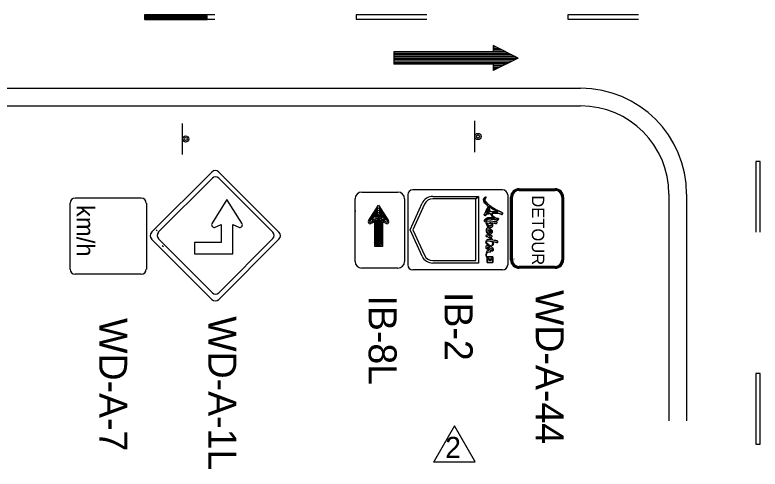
# Model space of a CAD drawing. Extents: x 1806 to 2022, y 110 to 389.
# Drawn here: x 1918.6 to 1969.6, y 190.1 to 221.2 of the extents above; entities that cross this region are included whole.
import ezdxf

# ---------------------------------------------------------------- set-up
doc = ezdxf.new("R2010")
doc.units = 0
for name, color, linetype in [('Level 10', 7, 'Continuous'), ('Level 2', 7, 'Continuous'), ('Level 44', 7, 'Continuous'), ('Level 50', 7, 'Continuous'), ('Level 53', 7, 'Continuous'), ('Level 60', 7, 'Continuous')]:
    doc.layers.add(name, color=color, linetype=linetype)

msp = doc.modelspace()

# ---------------------------------------------------------------- linework, layer by layer
at = {"layer": 'Level 10'}
for p, q in [((1927.465, 221.11), (1931.732, 221.11)), ((1927.465, 220.854), (1927.465, 221.11)), ((1927.465, 221.046), (1931.732, 221.046)), ((1927.465, 220.982), (1931.732, 220.982)), ((1927.465, 220.918), (1931.732, 220.918)), ((1927.465, 220.854), (1931.732, 220.854)), ((1931.732, 220.854), (1931.732, 221.11)), ((1895.86, 216.139), (1957.331, 216.139)), ((1895.86, 214.93), (1957.331, 214.93)), ((1963.38, 208.881), (1963.38, 193.374)), ((1964.59, 208.881), (1964.59, 193.374))]:
    msp.add_line(p, q, dxfattribs=at)
for radius in [7.258, 6.048]:
    msp.add_arc((1957.332, 208.881), radius, 0, 90, dxfattribs=at)
at = {"layer": 'Level 2'}
for p, q in [((1932.271, 221.163), (1927.433, 221.163)), ((1927.433, 221.163), (1927.433, 220.873)), ((1946.785, 221.163), (1941.947, 221.163)), ((1941.947, 221.163), (1941.947, 220.873)), ((1961.299, 221.163), (1956.461, 221.163)), ((1956.461, 221.163), (1956.461, 220.873)), ((1927.433, 220.873), (1932.271, 220.873)), ((1941.947, 220.873), (1946.785, 220.873)), ((1956.461, 220.873), (1961.299, 220.873)), ((1969.337, 211.124), (1969.337, 206.286)), ((1969.627, 211.124), (1969.337, 211.124)), ((1969.627, 206.286), (1969.627, 211.124)), ((1951.985, 209.179), (1945.831, 209.179)), ((1945.484, 208.832), (1945.484, 204.048)), ((1947.192, 208.737), (1950.32, 208.737)), ((1950.148, 208.566), (1947.192, 208.566)), ((1950.32, 208.737), (1950.148, 208.566)), ((1950.148, 208.566), (1950.32, 208.737)), ((1950.148, 204.343), (1950.148, 208.566)), ((1950.32, 208.737), (1950.32, 204.171)), ((1952.332, 208.832), (1952.332, 204.048)), ((1952.332, 208.832), (1952.332, 204.048)), ((1945.64, 206.454), (1946.465, 208.269)), ((1946.621, 208.198), (1945.828, 206.454)), ((1928.312, 206.367), (1928.234, 206.445)), ((1946.465, 204.64), (1945.64, 206.454)), ((1945.828, 206.454), (1946.621, 204.71)), ((1928.737, 205.274), (1928.659, 205.352)), ((1947.192, 204.343), (1950.148, 204.343)), ((1950.32, 204.171), (1947.192, 204.171)), ((1951.985, 203.701), (1945.831, 203.701)), ((1969.337, 196.61), (1969.337, 191.772)), ((1969.627, 196.61), (1969.337, 196.61)), ((1969.627, 191.772), (1969.627, 196.61)), ((1969.337, 191.772), (1969.627, 191.772))]:
    msp.add_line(p, q, dxfattribs=at)
for centre, radius, start, end in [((1945.831, 208.832), 0.347, 90, 180), ((1951.985, 208.832), 0.347, 360, 90), ((1947.192, 207.938), 0.799, 90, 155.5432), ((1947.192, 207.938), 0.628, 90, 155.5432), ((1947.192, 204.97), 0.799, 204.4568, 270), ((1947.192, 204.97), 0.628, 204.4568, 270), ((1945.831, 204.048), 0.347, 180, 270), ((1951.985, 204.048), 0.347, 270, 360)]:
    msp.add_arc(centre, radius, start, end, dxfattribs=at)
at = {"layer": 'Level 44'}
for p, q in [((1930.019, 213.734), (1930.019, 211.601)), ((1950.058, 213.907), (1950.058, 211.774)), ((1932.049, 210.401), (1927.931, 206.28)), ((1932.049, 210.397), (1932.049, 210.401)), ((1936.651, 206.28), (1932.537, 210.401)), ((1928.389, 206.28), (1932.094, 209.988)), ((1932.534, 209.988), (1936.237, 206.28)), ((1942.336, 209.022), (1944.801, 209.022)), ((1953.114, 209.142), (1955.579, 209.142)), ((1953.115, 209.256), (1955.58, 209.256)), ((1953.115, 209.191), (1955.58, 209.191)), ((1953.115, 209.137), (1955.58, 209.137)), ((1953.115, 209.137), (1955.58, 209.137)), ((1922.688, 208.625), (1922.689, 208.625)), ((1922.689, 208.625), (1927.219, 208.625)), ((1933.093, 208.511), (1932.071, 206.906)), ((1934.118, 206.903), (1933.093, 208.511)), ((1941.871, 204.275), (1941.871, 208.566)), ((1945.258, 208.566), (1945.258, 204.275)), ((1952.533, 204.39), (1952.533, 208.681)), ((1952.598, 204.39), (1952.598, 208.681)), ((1952.651, 204.395), (1952.651, 208.686)), ((1952.652, 204.39), (1952.652, 208.681)), ((1952.652, 204.39), (1952.652, 208.681)), ((1956.035, 208.686), (1956.035, 204.395)), ((1956.036, 208.681), (1956.036, 204.39)), ((1956.036, 208.681), (1956.036, 204.39)), ((1956.09, 208.681), (1956.09, 204.39)), ((1956.155, 208.681), (1956.155, 204.39)), ((1922.34, 203.747), (1922.34, 208.275)), ((1927.568, 208.275), (1927.568, 203.747)), ((1942.798, 207.055), (1943.481, 208.13)), ((1943.481, 208.13), (1944.168, 207.055)), ((1943.217, 206.982), (1942.909, 206.85)), ((1943.217, 205.305), (1943.217, 206.978)), ((1944.057, 206.854), (1943.75, 206.982)), ((1943.75, 206.982), (1943.75, 205.305)), ((1932.239, 206.604), (1932.702, 206.802)), ((1932.702, 206.802), (1932.702, 205.585)), ((1933.493, 204.794), (1933.493, 206.799)), ((1933.493, 206.799), (1933.951, 206.598)), ((1952.645, 206.32), (1952.645, 206.32)), ((1952.646, 206.315), (1952.646, 206.315)), ((1952.646, 206.315), (1952.646, 206.315)), ((1932.094, 202.139), (1928.389, 205.842)), ((1936.237, 205.842), (1932.534, 202.139)), ((1927.931, 205.794), (1932.049, 201.68)), ((1932.702, 205.585), (1930.858, 205.585)), ((1930.858, 205.585), (1930.858, 204.794)), ((1932.537, 201.68), (1936.651, 205.794)), ((1943.75, 205.305), (1943.217, 205.305)), ((1930.858, 204.794), (1933.493, 204.794)), ((1952.65, 204.394), (1952.652, 204.39)), ((1952.698, 204.418), (1952.7, 204.414)), ((1952.756, 204.447), (1952.758, 204.443)), ((1944.801, 203.823), (1942.336, 203.823)), ((1955.579, 203.943), (1953.114, 203.943)), ((1955.58, 203.938), (1953.115, 203.938)), ((1955.58, 203.938), (1953.115, 203.938)), ((1955.58, 203.884), (1953.115, 203.884)), ((1955.58, 203.819), (1953.115, 203.819)), ((1927.219, 203.397), (1922.689, 203.397))]:
    msp.add_line(p, q, dxfattribs=at)
for points in [[(1943.298, 205.395), (1943.298, 207.11), (1942.901, 206.94), (1942.858, 206.986), (1943.481, 207.972), (1944.113, 206.982), (1944.087, 206.935), (1943.665, 207.11), (1943.665, 205.391), (1943.298, 205.395), (1943.387, 205.476), (1943.387, 207.238), (1943.02, 207.089), (1943.481, 207.81), (1943.942, 207.089), (1943.575, 207.238), (1943.575, 205.476), (1943.387, 205.476), (1943.473, 205.566), (1943.473, 207.379), (1943.242, 207.281), (1943.481, 207.652), (1943.724, 207.272), (1943.588, 207.328), (1943.481, 207.498), (1943.374, 207.336), (1943.485, 207.37), (1943.588, 207.328), (1943.528, 207.242), (1943.485, 205.57), (1943.473, 205.566)], [(1941.867, 207.772), (1941.867, 207.7)], [(1943.298, 205.395), (1943.298, 207.11)]]:
    msp.add_lwpolyline(points, dxfattribs=at)
for centre, radius in [((1950.297, 212.836), 0.213), ((1930.258, 212.663), 0.213), ((1930.258, 212.663), 0.107), ((1950.297, 212.836), 0.107)]:
    msp.add_circle(centre, radius, dxfattribs=at)
for centre, radius, start, end in [((1932.293, 210.154), 0.345, 45, 135), ((1932.314, 209.767), 0.31, 45, 135), ((1942.333, 208.565), 0.462, 90, 180), ((1944.802, 208.565), 0.462, 0, 90), ((1953.111, 208.681), 0.581, 90, 180), ((1953.111, 208.681), 0.516, 90, 180), ((1953.11, 208.686), 0.462, 90, 180), ((1953.111, 208.681), 0.462, 90, 180), ((1953.111, 208.681), 0.462, 90, 180), ((1955.58, 208.686), 0.462, 0, 90), ((1955.581, 208.681), 0.581, 0, 90), ((1955.581, 208.681), 0.516, 0, 90), ((1955.581, 208.681), 0.462, 0, 90), ((1955.581, 208.681), 0.462, 0, 90), ((1922.688, 208.275), 0.349, 90, 180), ((1927.217, 208.275), 0.349, 360, 90), ((1932.238, 206.801), 0.198, 147.5014, 269.8949), ((1933.951, 206.797), 0.198, 269.8942, 32.4962), ((1942.908, 206.983), 0.132, 147.5038, 270.1058), ((1944.056, 206.986), 0.132, 270.1051, 32.4986), ((1928.177, 206.038), 0.345, 135, 225), ((1928.609, 206.062), 0.31, 135, 225), ((1936.018, 206.062), 0.31, 315, 45), ((1936.409, 206.038), 0.345, 315, 45), ((1942.333, 204.279), 0.462, 180, 270), ((1944.802, 204.279), 0.462, 270, 360), ((1953.111, 204.394), 0.581, 180, 270), ((1953.111, 204.394), 0.516, 180, 270), ((1953.11, 204.399), 0.462, 180, 270), ((1953.111, 204.394), 0.462, 180, 270), ((1953.111, 204.394), 0.462, 180, 270), ((1955.58, 204.399), 0.462, 270, 360), ((1955.581, 204.394), 0.462, 270, 360), ((1955.581, 204.394), 0.581, 270, 360), ((1955.581, 204.394), 0.516, 270, 360), ((1955.581, 204.394), 0.462, 270, 360), ((1922.688, 203.746), 0.349, 180, 270), ((1927.217, 203.746), 0.349, 270, 360), ((1932.314, 202.357), 0.31, 225, 315), ((1932.293, 201.921), 0.345, 225, 315)]:
    msp.add_arc(centre, radius, start, end, dxfattribs=at)
at = {"layer": 'Level 50'}
for p, q in [((1951.343, 218.632), (1944.517, 218.632)), ((1944.517, 218.632), (1944.517, 217.779)), ((1952.197, 218.632), (1944.517, 218.632)), ((1953.05, 218.205), (1951.343, 219.059)), ((1951.343, 219.059), (1951.343, 218.632)), ((1951.557, 218.952), (1951.343, 218.952)), ((1951.77, 218.845), (1951.343, 218.845)), ((1951.983, 218.739), (1951.343, 218.739)), ((1952.41, 218.525), (1944.517, 218.525)), ((1952.623, 218.419), (1944.517, 218.419)), ((1952.837, 218.312), (1944.517, 218.312)), ((1953.05, 218.205), (1944.517, 218.205)), ((1952.837, 218.099), (1944.517, 218.099)), ((1953.05, 218.205), (1951.343, 217.352)), ((1952.623, 217.992), (1944.517, 217.992)), ((1952.41, 217.885), (1944.517, 217.885)), ((1951.343, 217.779), (1944.517, 217.779)), ((1952.197, 217.779), (1944.517, 217.779)), ((1951.343, 217.779), (1951.343, 217.352)), ((1951.983, 217.672), (1951.343, 217.672)), ((1951.77, 217.565), (1951.343, 217.565)), ((1951.557, 217.459), (1951.343, 217.459))]:
    msp.add_line(p, q, dxfattribs=at)
at = {"layer": 'Level 53'}
msp.add_line((1950.915, 204.491), (1950.915, 204.592), dxfattribs=at)
msp.add_lwpolyline([(1950.915, 204.491), (1950.915, 204.196), (1951.322, 204.196), (1951.322, 204.604), (1950.915, 204.604), (1950.915, 204.592)], dxfattribs=at)
for points, degree in [([(1950.767, 207.045), (1950.774, 207.089), (1950.833, 207.147), (1950.931, 207.164), (1951.108, 207.195), (1951.282, 207.177), (1951.542, 207.125), (1951.591, 207.115), (1951.676, 207.082), (1951.692, 207.188), (1951.697, 207.222), (1951.681, 207.204), (1951.636, 207.214), (1951.443, 207.255), (1951.303, 207.413), (1951.21, 207.572), (1951.431, 207.588), (1951.677, 207.581), (1951.828, 207.54), (1951.955, 207.505), (1951.931, 207.463), (1951.958, 207.515), (1951.986, 207.569), (1951.949, 207.628), (1951.854, 207.675), (1951.76, 207.723), (1951.245, 207.941), (1950.898, 208.29), (1950.721, 208.469), (1950.812, 208.631), (1950.839, 208.663), (1950.862, 208.689), (1950.827, 208.699), (1950.792, 208.666), (1950.636, 208.522), (1950.726, 208.311), (1950.803, 208.234), (1951.015, 208.022), (1951.472, 207.775), (1951.666, 207.675), (1951.557, 207.684), (1951.373, 207.687), (1951.159, 207.667), (1951.106, 207.775), (1951.075, 207.872), (1951.063, 207.918), (1951.05, 207.967), (1951.03, 207.998), (1951.007, 207.999), (1950.982, 208), (1950.961, 207.966), (1950.938, 207.918), (1950.898, 207.833), (1950.779, 207.582), (1950.743, 207.52), (1950.713, 207.468), (1950.737, 207.442), (1950.77, 207.426), (1950.813, 207.406), (1950.838, 207.462), (1950.854, 207.516), (1950.927, 207.537), (1951.024, 207.554), (1951.132, 207.565), (1951.21, 207.437), (1951.315, 207.312), (1951.445, 207.24), (1951.336, 207.258), (1950.965, 207.305), (1950.809, 207.188), (1950.774, 207.162), (1950.736, 207.105), (1950.742, 207.049), (1950.745, 207.023), (1950.762, 207.01), (1950.767, 207.012), (1950.773, 207.015), (1950.765, 207.03), (1950.767, 207.045)], 3), ([(1951.21, 207.572), (1951.431, 207.588), (1951.677, 207.581), (1951.828, 207.54), (1951.955, 207.505), (1951.931, 207.463), (1951.958, 207.515), (1951.986, 207.569), (1951.949, 207.628), (1951.854, 207.675), (1951.76, 207.723), (1951.245, 207.941), (1950.898, 208.29), (1950.721, 208.469), (1950.812, 208.631), (1950.839, 208.663), (1950.862, 208.689), (1950.827, 208.699), (1950.792, 208.666), (1950.636, 208.522), (1950.726, 208.311), (1950.803, 208.234), (1951.015, 208.022), (1951.472, 207.775), (1951.666, 207.675)], 3), ([(1951.159, 207.667), (1951.106, 207.775), (1951.075, 207.872), (1951.063, 207.918), (1951.05, 207.967), (1951.03, 207.998), (1951.007, 207.999), (1950.982, 208), (1950.961, 207.966), (1950.938, 207.918), (1950.898, 207.833), (1950.779, 207.582), (1950.743, 207.52), (1950.713, 207.468), (1950.737, 207.442), (1950.77, 207.426), (1950.813, 207.406), (1950.838, 207.462), (1950.854, 207.516)], 3), ([(1950.884, 207.625), (1950.904, 207.68), (1950.936, 207.759), (1950.989, 207.862)], 2), ([(1950.989, 207.862), (1951.009, 207.806), (1951.039, 207.734), (1951.079, 207.658), (1950.993, 207.648), (1950.93, 207.637), (1950.884, 207.625), (1950.904, 207.68), (1950.936, 207.759), (1950.989, 207.862)], 3), ([(1950.989, 207.862), (1951.009, 207.806), (1951.039, 207.734), (1951.079, 207.658)], 2), ([(1950.767, 207.045), (1950.774, 207.089), (1950.833, 207.147), (1950.931, 207.164), (1951.108, 207.195), (1951.282, 207.177), (1951.542, 207.125), (1951.591, 207.115), (1951.676, 207.082), (1951.692, 207.188), (1951.697, 207.222), (1951.681, 207.204), (1951.636, 207.214), (1951.443, 207.255), (1951.303, 207.413), (1951.21, 207.572)], 3), ([(1950.854, 207.516), (1950.927, 207.537), (1951.024, 207.554), (1951.132, 207.565)], 2), ([(1951.079, 207.658), (1950.993, 207.648), (1950.93, 207.637), (1950.884, 207.625)], 2), ([(1951.132, 207.565), (1951.21, 207.437), (1951.315, 207.312), (1951.445, 207.24)], 2), ([(1951.666, 207.675), (1951.557, 207.684), (1951.373, 207.687), (1951.159, 207.667)], 2), ([(1951.445, 207.24), (1951.336, 207.258), (1950.965, 207.305), (1950.809, 207.188), (1950.774, 207.162), (1950.736, 207.105), (1950.742, 207.049), (1950.745, 207.023), (1950.762, 207.01), (1950.767, 207.012), (1950.773, 207.015), (1950.765, 207.03), (1950.767, 207.045)], 3), ([(1950.948, 207.017), (1950.933, 207.063), (1950.899, 207.081), (1950.862, 207.022), (1950.837, 206.982), (1950.829, 206.892), (1950.873, 206.802), (1950.889, 206.769), (1950.912, 206.741), (1950.938, 206.718)], 3), ([(1950.881, 206.897), (1950.878, 206.912), (1950.879, 206.924), (1950.88, 206.934)], 2), ([(1950.88, 206.934), (1950.885, 206.928), (1950.893, 206.924), (1950.901, 206.924), (1950.907, 206.924), (1950.913, 206.924), (1950.919, 206.924)], 3), ([(1950.926, 206.822), (1950.902, 206.845), (1950.885, 206.87), (1950.881, 206.897)], 2), ([(1950.919, 206.924), (1950.92, 206.901), (1950.922, 206.865), (1950.926, 206.822)], 2), ([(1951.104, 206.947), (1951.207, 206.939), (1951.334, 206.922), (1951.451, 206.899), (1951.5, 206.889), (1951.586, 206.856), (1951.602, 206.962), (1951.607, 206.996), (1951.591, 206.991), (1951.546, 206.988), (1951.484, 206.984), (1951.112, 207.052), (1950.948, 207.017)], 3), ([(1950.971, 206.789), (1950.967, 206.83), (1950.963, 206.874), (1950.959, 206.92)], 2), ([(1950.959, 206.92), (1951.09, 206.903), (1951.272, 206.835), (1951.242, 206.75), (1951.226, 206.701), (1951.073, 206.727), (1950.971, 206.789)], 3), ([(1950.983, 206.685), (1951.106, 206.609), (1951.272, 206.616), (1951.3, 206.726), (1951.332, 206.855), (1951.207, 206.92), (1951.104, 206.947)], 3), ([(1950.964, 206.556), (1950.892, 206.547), (1950.837, 206.5), (1950.847, 206.391), (1950.862, 206.237), (1951.052, 206.1), (1951.143, 206.048)], 3), ([(1951.063, 205.972), (1951.113, 205.962), (1951.169, 205.946), (1951.207, 205.945), (1951.246, 205.944), (1951.255, 205.971), (1951.258, 205.982), (1951.265, 206.005), (1951.253, 206.033), (1951.215, 206.06), (1951.124, 206.125), (1950.98, 206.207), (1950.92, 206.331), (1950.876, 206.42), (1950.92, 206.459), (1950.987, 206.461)], 3), ([(1950.938, 206.718), (1950.945, 206.664), (1950.954, 206.607), (1950.964, 206.556)], 2), ([(1951.004, 206.557), (1950.996, 206.594), (1950.989, 206.637), (1950.983, 206.685)], 2), ([(1950.987, 206.461), (1950.992, 206.443), (1950.998, 206.428), (1951.004, 206.414), (1951.075, 206.253), (1951.183, 206.198), (1951.249, 206.239), (1951.311, 206.278), (1951.292, 206.389), (1951.2, 206.477), (1951.154, 206.52), (1951.076, 206.553), (1951.004, 206.557)], 3), ([(1951.191, 206.375), (1951.242, 206.321), (1951.238, 206.294), (1951.224, 206.287), (1951.195, 206.271), (1951.093, 206.335), (1951.036, 206.457)], 3), ([(1951.036, 206.457), (1951.092, 206.446), (1951.152, 206.417), (1951.191, 206.375)], 2), ([(1951.143, 206.048), (1951.045, 206.057), (1950.831, 206.121), (1950.842, 206.012), (1950.846, 205.97), (1950.853, 205.988), (1950.89, 205.985), (1951.019, 205.976), (1951.128, 205.869), (1951.195, 205.762)], 3), ([(1951.305, 205.746), (1951.255, 205.833), (1951.172, 205.913), (1951.063, 205.972)], 2), ([(1951.195, 205.762), (1951.037, 205.781), (1950.896, 205.774), (1950.851, 205.703), (1950.769, 205.571), (1950.986, 205.384), (1951.119, 205.281)], 3), ([(1951.119, 205.281), (1951.001, 205.334), (1950.85, 205.363), (1950.827, 205.285), (1950.8, 205.192), (1950.953, 205.12), (1951.07, 205.035)], 3), ([(1950.879, 204.718), (1950.879, 204.885), (1951.009, 204.928), (1951.073, 204.936), (1951.116, 204.941), (1951.178, 204.932), (1951.17, 205.006), (1951.164, 205.058), (1951.063, 205.105), (1950.978, 205.17), (1950.906, 205.226), (1950.913, 205.251), (1950.975, 205.238), (1951.053, 205.222), (1951.237, 205.157), (1951.25, 205.082), (1951.256, 205.048), (1951.196, 205.035), (1951.234, 205.019), (1951.272, 205.003), (1951.354, 205.018), (1951.354, 205.095), (1951.354, 205.149), (1951.296, 205.214), (1951.231, 205.268), (1951.174, 205.314), (1950.829, 205.549), (1950.903, 205.647), (1950.938, 205.693), (1951.08, 205.69), (1951.247, 205.661)], 3), ([(1951.247, 205.661), (1951.292, 205.544), (1951.278, 205.447), (1951.251, 205.392), (1951.238, 205.365), (1951.24, 205.361), (1951.27, 205.372), (1951.314, 205.39), (1951.382, 205.483), (1951.351, 205.63), (1951.35, 205.634), (1951.349, 205.637), (1951.348, 205.641)], 3), ([(1951.348, 205.641), (1951.403, 205.629), (1951.458, 205.615), (1951.512, 205.6), (1951.561, 205.586), (1951.646, 205.546), (1951.662, 205.651), (1951.667, 205.685), (1951.651, 205.671), (1951.606, 205.682), (1951.522, 205.702), (1951.414, 205.728), (1951.305, 205.746)], 3), ([(1951.07, 205.035), (1950.986, 205.025), (1950.841, 204.969), (1950.841, 204.743), (1950.841, 204.641), (1950.87, 204.555), (1950.915, 204.491)], 3), ([(1950.915, 204.592), (1950.893, 204.629), (1950.879, 204.672), (1950.879, 204.718)], 2), ([(1951.322, 204.604), (1951.322, 204.604), (1950.915, 204.604), (1950.915, 204.604), (1950.915, 204.604), (1950.915, 204.592), (1950.915, 204.592), (1950.968, 204.503), (1951.069, 204.444), (1951.153, 204.444), (1951.224, 204.444), (1951.221, 204.482), (1951.231, 204.478), (1951.26, 204.466), (1951.243, 204.376), (1951.142, 204.37), (1951.055, 204.366), (1950.972, 204.411), (1950.915, 204.491), (1950.915, 204.491), (1950.915, 204.196), (1950.915, 204.196), (1950.915, 204.196), (1951.322, 204.196), (1951.322, 204.196), (1951.322, 204.196), (1951.322, 204.604), (1951.322, 204.604)], 3), ([(1950.915, 204.592), (1950.968, 204.503), (1951.069, 204.444), (1951.153, 204.444), (1951.224, 204.444), (1951.221, 204.482), (1951.231, 204.478), (1951.26, 204.466), (1951.243, 204.376), (1951.142, 204.37), (1951.055, 204.366), (1950.972, 204.411), (1950.915, 204.491)], 3)]:
    msp.add_open_spline(points, degree=degree, dxfattribs=at)
at = {"layer": 'Level 60'}
for points in [[(1948.675, 193.019), (1947.282, 190.594)], [(1950.069, 190.594), (1948.675, 193.019)], [(1947.282, 190.594), (1947.256, 190.549), (1950.095, 190.549), (1950.069, 190.594)]]:
    msp.add_lwpolyline(points, dxfattribs=at)

# ---------------------------------------------------------------- texts
at = {"layer": 'Level 44'}
for s, height, p in [('DETOUR', 0.848, (1953.986, 208.81)), ('km/h', 1.218, (1922.782, 208.145))]:
    msp.add_text(s, height=height, rotation=270, dxfattribs=at).set_placement(p)
at = {"layer": 'Level 50'}
for s, p in [('WD-A-44', (1954.257, 202.324)), ('IB-2', (1948.006, 202.185)), ('IB-8L', (1942.801, 201.949)), ('WD-A-7', (1924.337, 200.4)), ('WD-A-1L', (1931.819, 200.529))]:
    msp.add_text(s, height=1.9199, rotation=270, dxfattribs=at).set_placement(p)
at = {"layer": 'Level 60'}
msp.add_text('2', height=1.448, rotation=360, dxfattribs=at).set_placement((1948.048, 190.818))

doc.saveas('drawing.dxf')
